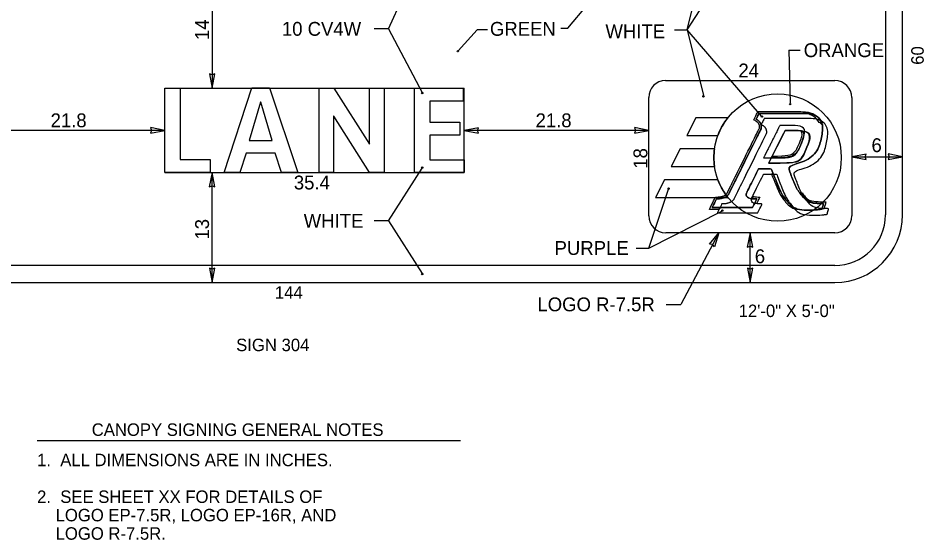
# Model space of a CAD drawing. Extents: x 60712 to 61344, y 9358 to 10016.
# Drawn here: x 60817.5 to 61020.9, y 9406.3 to 9523.5 of the extents above; entities that cross this region are included whole.
import ezdxf

# ---------------------------------------------------------------- set-up
doc = ezdxf.new("R2010")
doc.units = 0
for name, color, linetype in [('1', 7, 'Continuous'), ('52', 7, 'Continuous'), ('Default', 7, 'Continuous'), ('SignPanel', 7, 'Continuous'), ('TextNotes', 7, 'Continuous')]:
    doc.layers.add(name, color=color, linetype=linetype)

msp = doc.modelspace()

# ---------------------------------------------------------------- linework, layer by layer
at = {"layer": '1'}
for p, q in [((60967.73, 9520.86), (60980.08, 9540)), ((60900.69, 9521.08), (60907.15, 9535.36)), ((60967.73, 9520.86), (60971.4, 9535.64)), ((60940.98, 9521.26), (60945.38, 9526.45)), ((60900.69, 9521.08), (60897.49, 9521.08)), ((60900.69, 9521.08), (60908.25, 9506.8)), ((60920.6, 9520.86), (60916.35, 9516.16)), ((60922.88, 9520.86), (60920.6, 9520.86)), ((60939.35, 9521.26), (60940.98, 9521.26)), ((60964.88, 9520.86), (60967.73, 9520.86)), ((60967.73, 9520.86), (60971.4, 9506.08)), ((60984.44, 9501.48), (60967.73, 9520.86)), ((60990.58, 9516.29), (60993.13, 9516.29)), ((60990.58, 9516.29), (60990.88, 9504.35)), ((61004.73, 9492.36), (61016.13, 9492.36)), ((60900.69, 9477.96), (60908.25, 9489.76)), ((60959.13, 9471.85), (60963.59, 9485.04)), ((60959.13, 9471.85), (60975.54, 9480.16)), ((60900.69, 9477.96), (60897.49, 9477.96)), ((60900.69, 9477.96), (60908.25, 9466.16)), ((60974.83, 9475.26), (60966.36, 9459.17)), ((60981.88, 9464.1), (60981.88, 9475.26)), ((60956.28, 9471.85), (60959.13, 9471.85)), ((60963.03, 9459.17), (60966.36, 9459.17))]:
    msp.add_line(p, q, dxfattribs=at)
for centre, major_axis, ratio in [((60916.25, 9516.05), (0, 0.157), 0.906668), ((60908.25, 9506.64), (0.163, 0), 0.961364), ((60971.4, 9505.92), (0, 0.157), 0.906668), ((60990.88, 9504.19), (0, 0.157), 0.906668), ((60984.54, 9501.37), (0, 0.157), 0.906668), ((60908.25, 9489.91), (0.164, 0), 0.960359), ((60963.59, 9485.2), (0, 0.157), 0.906668), ((60975.65, 9480.27), (0, 0.157), 0.906668), ((60908.25, 9466), (0.163, 0), 0.961364)]:
    msp.add_ellipse(centre, major_axis=major_axis, ratio=ratio, dxfattribs=at)
at = {"layer": '52'}
for p, q in [((60861.05, 9510.73), (60860.45, 9510.98)), ((60860.45, 9510.98), (60861.05, 9507.75)), ((60861.05, 9507.75), (60861.67, 9510.98)), ((60861.67, 9510.98), (60861.05, 9510.73)), ((60850.44, 9498.28), (60847.22, 9498.9)), ((60847.22, 9498.9), (60847.46, 9498.28)), ((60847.46, 9498.28), (60847.22, 9497.68)), ((60847.22, 9497.68), (60850.44, 9498.28)), ((60920.9, 9498.88), (60917.68, 9498.28)), ((60917.68, 9498.28), (60920.9, 9497.66)), ((60920.66, 9498.28), (60920.9, 9498.88)), ((60920.9, 9497.66), (60920.66, 9498.28)), ((60959.13, 9498.28), (60955.9, 9498.9)), ((60955.9, 9498.9), (60956.15, 9498.28)), ((60956.15, 9498.28), (60955.9, 9497.68)), ((60955.9, 9497.68), (60959.13, 9498.28)), ((61007.95, 9492.96), (61004.73, 9492.36)), ((61004.73, 9492.36), (61007.95, 9491.73)), ((61007.7, 9492.36), (61007.95, 9492.96)), ((61007.95, 9491.73), (61007.7, 9492.36)), ((61016.13, 9492.36), (61012.9, 9492.98)), ((61012.9, 9492.98), (61013.15, 9492.36)), ((61013.15, 9492.36), (61012.9, 9491.76)), ((61012.9, 9491.76), (61016.13, 9492.36)), ((60861.05, 9488.8), (60860.42, 9485.58)), ((60861.65, 9485.58), (60861.05, 9488.8)), ((60860.42, 9485.58), (60861.05, 9485.82)), ((60861.05, 9485.82), (60861.65, 9485.58)), ((60972.8, 9472.69), (60974.83, 9475.26)), ((60974.83, 9475.26), (60973.88, 9472.12)), ((60981.88, 9475.26), (60981.26, 9472.04)), ((60982.48, 9472.04), (60981.88, 9475.26)), ((60973.44, 9472.62), (60972.8, 9472.69)), ((60973.88, 9472.12), (60973.44, 9472.62)), ((60981.26, 9472.04), (60981.88, 9472.28)), ((60981.88, 9472.28), (60982.48, 9472.04)), ((60861.05, 9467.08), (60860.45, 9467.32)), ((60860.45, 9467.32), (60861.05, 9464.1)), ((60861.05, 9464.1), (60861.67, 9467.32)), ((60861.67, 9467.32), (60861.05, 9467.08)), ((60981.88, 9467.08), (60981.28, 9467.32)), ((60981.28, 9467.32), (60981.88, 9464.1)), ((60981.88, 9464.1), (60982.5, 9467.32)), ((60982.5, 9467.32), (60981.88, 9467.08))]:
    msp.add_line(p, q, dxfattribs=at)
at = {"layer": 'Default'}
for p, q in [((60850.44, 9507.75), (60917.68, 9507.75)), ((60850.44, 9488.8), (60850.44, 9507.66)), ((60917.68, 9488.8), (60917.68, 9507.75)), ((60850.44, 9488.8), (60917.68, 9488.8))]:
    msp.add_line(p, q, dxfattribs=at)
at = {"layer": 'SignPanel'}
for p, q in [((61012.3, 9562.9), (61012.3, 9479.3)), ((61016.1, 9479.3), (61016.1, 9562.9)), ((60861.05, 9534.4), (60861.05, 9507.75)), ((60962.88, 9509.46), (61000.92, 9509.46)), ((60959.13, 9479.06), (60959.13, 9505.66)), ((61004.73, 9505.66), (61004.73, 9479.06)), ((60850.44, 9498.28), (60808.53, 9498.28)), ((60959.13, 9498.28), (60917.68, 9498.28)), ((60982.2, 9495.19), (60982.22, 9495.22)), ((60982.57, 9495.05), (60982.56, 9495.01)), ((60861.05, 9464.1), (60861.05, 9488.8)), ((60987.13, 9488.46), (60986.7, 9488.46)), ((60975.1, 9480.92), (60974.9, 9480.53)), ((61000.92, 9475.26), (60962.93, 9475.26)), ((61000.9, 9467.9), (60757.74, 9467.9)), ((60757.74, 9464.1), (61000.9, 9464.1))]:
    msp.add_line(p, q, dxfattribs=at)
for points in [[(60850.44, 9488.8), (60850.44, 9507.75), (60853.87, 9507.75), (60853.87, 9491.7), (60860.65, 9491.7), (60860.65, 9488.8), (60850.44, 9488.8)], [(60876.62, 9488.8), (60875.23, 9493.13), (60868.68, 9493.13), (60867.3, 9488.8), (60863.73, 9488.8), (60869.95, 9507.8), (60873.95, 9507.8), (60880.29, 9488.8), (60876.62, 9488.8)], [(60896.41, 9488.8), (60888.38, 9501.5), (60888.33, 9501.5), (60888.33, 9488.8), (60885.08, 9488.8), (60885.08, 9507.75), (60888.38, 9507.75), (60896.38, 9495.19), (60896.4, 9495.19), (60896.41, 9507.75), (60899.68, 9507.75), (60899.68, 9488.8), (60896.41, 9488.8)], [(60906.55, 9488.8), (60906.55, 9507.75), (60917.41, 9507.75), (60917.41, 9504.85), (60909.95, 9504.85), (60909.95, 9500.08), (60916.69, 9500.08), (60916.69, 9497.17), (60909.95, 9497.17), (60909.95, 9491.65), (60917.68, 9491.65), (60917.68, 9488.8), (60906.55, 9488.8)], [(60871.99, 9504.58), (60871.9, 9504.58), (60869.36, 9495.98), (60874.53, 9495.98), (60871.99, 9504.58)], [(60976.9, 9501.1), (60969.72, 9501.1), (60967.7, 9497.12), (60974.65, 9497.12)], [(60991.65, 9498.25), (60989.75, 9498.25), (60986.05, 9490.93), (60987.26, 9490.93)], [(60973.9, 9494.14), (60966.18, 9494.14), (60964.15, 9490.17), (60973.9, 9490.17)], [(60974.65, 9487.19), (60962.63, 9487.19), (60960.61, 9483.21), (60976.9, 9483.21)]]:
    msp.add_lwpolyline(points, dxfattribs=at)
msp.add_circle((60988.06, 9492.16), 14.31, dxfattribs=at)
for centre, radius, start, end in [((60962.93, 9505.66), 3.8, 90.6597, 180), ((61000.92, 9505.66), 3.8, 0, 90), ((60988.06, 9492.16), 14.31, 141.3093, 159.6812), ((60995.26, 9496.73), 3.97, 44.1751, 57.1095), ((60988.06, 9492.16), 14.31, 172.0148, 187.9874), ((60988.06, 9492.16), 14.31, 200.3256, 218.6989), ((61006.06, 9490.82), 14.13, 207.7086, 215.0356), ((60983.39, 9482.97), 1.08, 153.9516, 176.8436), ((60983.99, 9484.1), 2.29, 244.3445, 254.3668), ((60996.12, 9485.35), 6.28, 217.4324, 229.8152), ((60999.29, 9490.89), 10.19, 263.2057, 265.4782), ((60962.93, 9479.06), 3.8, 180, 270), ((61000.9, 9479.3), 15.2, 270, 0), ((61000.9, 9479.3), 11.4, 270, 0), ((61000.92, 9479.06), 3.8, 270, 360)]:
    msp.add_arc(centre, radius, start, end, dxfattribs=at)
for points, degree in [([(60982.22, 9495.22), (60983.25, 9497.3), (60983.98, 9498.77), (60983.98, 9498.77), (60983.98, 9498.77), (60983.99, 9498.89), (60983.99, 9498.89), (60983.99, 9498.89), (60983.99, 9499.07), (60983.99, 9499.07), (60983.99, 9499.07), (60983.99, 9499.2), (60983.99, 9499.2), (60983.99, 9499.2), (60983.98, 9499.34), (60983.98, 9499.34), (60983.98, 9499.34), (60983.94, 9499.51), (60983.94, 9499.51), (60983.94, 9499.51), (60983.87, 9499.7), (60983.87, 9499.7), (60983.87, 9499.7), (60983.8, 9499.81), (60983.8, 9499.81), (60983.8, 9499.81), (60983.67, 9499.98), (60983.67, 9499.98), (60983.67, 9499.98), (60983.48, 9500.15), (60983.48, 9500.15), (60983.48, 9500.15), (60983.26, 9500.3), (60983.26, 9500.3), (60983.26, 9500.3), (60982.72, 9500.63), (60982.72, 9500.63), (60982.72, 9500.63), (60983.65, 9502.48), (60983.65, 9502.48), (60983.65, 9502.48), (60992.81, 9502.48), (60992.81, 9502.48), (60995.67, 9502.48), (60997.43, 9501.23), (60998.1, 9499.5)], 3), ([(60983.76, 9489.61), (60983.76, 9489.61), (60981.33, 9484.71), (60981.33, 9484.71), (60980.89, 9483.99), (60981.21, 9482.91), (60983.43, 9482.91), (60983.43, 9482.91), (60982.44, 9480.92), (60982.44, 9480.92), (60982.44, 9480.92), (60973.37, 9480.92), (60973.37, 9480.92), (60973.37, 9480.92), (60974.37, 9482.91), (60974.37, 9482.91), (60974.37, 9482.91), (60974.65, 9482.91), (60974.65, 9482.91), (60974.65, 9482.91), (60974.95, 9482.92), (60974.95, 9482.92), (60974.95, 9482.92), (60975.21, 9482.95), (60975.21, 9482.95), (60975.21, 9482.95), (60975.65, 9483.04), (60975.65, 9483.04), (60975.65, 9483.04), (60975.99, 9483.13), (60975.99, 9483.13), (60975.99, 9483.13), (60976.27, 9483.25), (60976.27, 9483.25), (60976.27, 9483.25), (60976.47, 9483.36), (60976.47, 9483.36), (60976.47, 9483.36), (60976.67, 9483.48), (60976.67, 9483.48), (60976.67, 9483.48), (60976.87, 9483.67), (60976.87, 9483.67), (60976.87, 9483.67), (60977.02, 9483.86), (60977.02, 9483.86), (60977.02, 9483.86), (60977.07, 9483.97), (60977.07, 9483.97), (60977.07, 9483.97), (60984.36, 9498.65), (60984.36, 9498.65), (60984.36, 9498.65), (60984.39, 9498.87), (60984.39, 9498.87), (60984.39, 9498.87), (60984.39, 9499.07), (60984.39, 9499.07), (60984.39, 9499.07), (60984.39, 9499.22), (60984.39, 9499.22), (60984.39, 9499.22), (60984.38, 9499.4), (60984.38, 9499.4), (60984.38, 9499.4), (60984.32, 9499.63), (60984.32, 9499.63), (60984.32, 9499.63), (60984.23, 9499.87), (60984.23, 9499.87), (60984.23, 9499.87), (60984.13, 9500.03), (60984.13, 9500.03), (60984.13, 9500.03), (60983.96, 9500.26), (60983.96, 9500.26), (60983.96, 9500.26), (60983.72, 9500.46), (60983.72, 9500.46), (60983.72, 9500.46), (60983.48, 9500.64), (60983.48, 9500.64), (60983.48, 9500.64), (60983.24, 9500.78), (60983.24, 9500.78), (60983.24, 9500.78), (60983.89, 9502.08), (60983.89, 9502.08), (60983.89, 9502.08), (60992.81, 9502.08), (60992.81, 9502.08), (60996.85, 9502.08), (60998.48, 9499.63), (60997.91, 9496.76), (60997.28, 9493.58), (60994.23, 9491.09), (60990.08, 9490.36), (60990.99, 9488.67), (60992.07, 9485.42), (60993.63, 9483.48), (60994.68, 9482.17), (60996.52, 9481.85), (60998.39, 9481.85), (60998.39, 9481.85), (60998.03, 9480.58), (60998.03, 9480.58), (60998.03, 9480.58), (60997.78, 9480.54), (60997.78, 9480.54), (60996.75, 9480.4), (60996.09, 9480.37), (60995.33, 9480.37), (60992.8, 9480.37), (60991.25, 9481.1), (60990.06, 9482.58), (60988.67, 9484.31), (60987.33, 9487.99), (60986.66, 9489.61), (60986.66, 9489.61), (60983.76, 9489.61), (60983.76, 9489.61)], 3), ([(60984.92, 9488.46), (60984.92, 9488.46), (60982.49, 9483.55), (60982.49, 9483.55), (60982.05, 9482.84), (60982.36, 9481.75), (60984.59, 9481.75), (60984.59, 9481.75), (60983.59, 9479.77), (60983.59, 9479.77), (60983.59, 9479.77), (60974.53, 9479.77), (60974.53, 9479.77), (60974.53, 9479.77), (60975.52, 9481.75), (60975.52, 9481.75), (60975.52, 9481.75), (60975.8, 9481.75), (60975.8, 9481.75), (60975.8, 9481.75), (60976.11, 9481.77), (60976.11, 9481.77), (60976.11, 9481.77), (60976.36, 9481.79), (60976.36, 9481.79), (60976.36, 9481.79), (60976.8, 9481.89), (60976.8, 9481.89), (60976.8, 9481.89), (60977.14, 9481.98), (60977.14, 9481.98), (60977.14, 9481.98), (60977.42, 9482.1), (60977.42, 9482.1), (60977.42, 9482.1), (60977.62, 9482.21), (60977.62, 9482.21), (60977.62, 9482.21), (60977.82, 9482.33), (60977.82, 9482.33), (60977.82, 9482.33), (60978.02, 9482.52), (60978.02, 9482.52), (60978.02, 9482.52), (60978.17, 9482.71), (60978.17, 9482.71), (60978.17, 9482.71), (60978.22, 9482.81), (60978.22, 9482.81), (60978.22, 9482.81), (60985.51, 9497.5), (60985.51, 9497.5), (60985.51, 9497.5), (60985.54, 9497.71), (60985.54, 9497.71), (60985.54, 9497.71), (60985.54, 9497.91), (60985.54, 9497.91), (60985.54, 9497.91), (60985.54, 9498.06), (60985.54, 9498.06), (60985.54, 9498.06), (60985.53, 9498.25), (60985.53, 9498.25), (60985.53, 9498.25), (60985.47, 9498.48), (60985.47, 9498.48), (60985.47, 9498.48), (60985.38, 9498.72), (60985.38, 9498.72), (60985.38, 9498.72), (60985.29, 9498.88), (60985.29, 9498.88), (60985.29, 9498.88), (60985.11, 9499.11), (60985.11, 9499.11), (60985.11, 9499.11), (60984.87, 9499.31), (60984.87, 9499.31), (60984.87, 9499.31), (60984.63, 9499.48), (60984.63, 9499.48), (60984.63, 9499.48), (60984.39, 9499.63), (60984.39, 9499.63), (60984.39, 9499.63), (60985.05, 9500.93), (60985.05, 9500.93), (60985.05, 9500.93), (60993.96, 9500.93), (60993.96, 9500.93), (60998.01, 9500.93), (60999.63, 9498.48), (60999.06, 9495.61), (60998.43, 9492.42), (60995.38, 9489.94), (60991.23, 9489.21), (60992.14, 9487.52), (60993.23, 9484.27), (60994.78, 9482.33), (60995.83, 9481.02), (60997.67, 9480.69), (60999.55, 9480.69), (60999.55, 9480.69), (60999.18, 9479.42), (60999.18, 9479.42), (60999.18, 9479.42), (60998.94, 9479.39), (60998.94, 9479.39), (60997.91, 9479.25), (60997.24, 9479.22), (60996.48, 9479.22), (60993.96, 9479.22), (60992.41, 9479.94), (60991.21, 9481.43), (60989.83, 9483.16), (60988.48, 9486.84), (60987.82, 9488.46), (60987.82, 9488.46), (60984.92, 9488.46), (60984.92, 9488.46)], 3), ([(60982.57, 9495.05), (60983.6, 9497.12), (60984.36, 9498.65), (60984.36, 9498.65), (60984.36, 9498.65), (60984.39, 9498.87), (60984.39, 9498.87), (60984.39, 9498.87), (60984.39, 9499.07), (60984.39, 9499.07), (60984.39, 9499.07), (60984.39, 9499.22), (60984.39, 9499.22), (60984.39, 9499.22), (60984.38, 9499.4), (60984.38, 9499.4), (60984.38, 9499.4), (60984.32, 9499.63), (60984.32, 9499.63), (60984.32, 9499.63), (60984.23, 9499.87), (60984.23, 9499.87), (60984.23, 9499.87), (60984.13, 9500.03), (60984.13, 9500.03), (60984.13, 9500.03), (60983.96, 9500.26), (60983.96, 9500.26), (60983.96, 9500.26), (60983.72, 9500.46), (60983.72, 9500.46), (60983.72, 9500.46), (60983.48, 9500.64), (60983.48, 9500.64), (60983.48, 9500.64), (60983.24, 9500.78), (60983.24, 9500.78), (60983.24, 9500.78), (60983.89, 9502.08), (60983.89, 9502.08), (60983.89, 9502.08), (60992.81, 9502.08), (60992.81, 9502.08), (60996.85, 9502.08), (60998.48, 9499.63), (60997.91, 9496.76), (60997.28, 9493.58), (60994.23, 9491.09), (60990.08, 9490.36), (60990.99, 9488.67), (60992.07, 9485.42), (60993.63, 9483.48), (60994.68, 9482.17), (60996.52, 9481.85), (60998.39, 9481.85), (60998.39, 9481.85), (60998.03, 9480.58), (60998.03, 9480.58), (60998.03, 9480.58), (60997.78, 9480.54), (60997.78, 9480.54), (60996.75, 9480.4), (60996.09, 9480.37), (60995.33, 9480.37), (60992.8, 9480.37), (60991.25, 9481.1), (60990.06, 9482.58), (60988.67, 9484.31), (60987.33, 9487.99), (60986.66, 9489.61), (60986.66, 9489.61), (60983.76, 9489.61), (60983.76, 9489.61)], 3), ([(60997.41, 9500.06), (60996.64, 9501.28), (60995.12, 9502.08), (60992.81, 9502.08), (60992.81, 9502.08), (60983.89, 9502.08), (60983.89, 9502.08), (60983.89, 9502.08), (60983.24, 9500.78), (60983.24, 9500.78), (60983.24, 9500.78), (60983.48, 9500.64), (60983.48, 9500.64), (60983.48, 9500.64), (60983.72, 9500.46), (60983.72, 9500.46), (60983.72, 9500.46), (60983.96, 9500.26), (60983.96, 9500.26), (60983.96, 9500.26), (60984.13, 9500.03), (60984.13, 9500.03), (60984.13, 9500.03), (60984.23, 9499.87), (60984.23, 9499.87), (60984.23, 9499.87), (60984.32, 9499.63), (60984.32, 9499.63), (60984.32, 9499.63), (60984.38, 9499.4), (60984.38, 9499.4), (60984.38, 9499.4), (60984.39, 9499.22), (60984.39, 9499.22), (60984.39, 9499.22), (60984.39, 9499.07), (60984.39, 9499.07), (60984.39, 9499.07), (60984.39, 9498.87), (60984.39, 9498.87), (60984.39, 9498.87), (60984.36, 9498.65), (60984.36, 9498.65), (60984.36, 9498.65), (60983.6, 9497.12), (60982.57, 9495.05)], 3), ([(60985.61, 9493.5), (60985.19, 9492.66), (60984.9, 9492.08), (60984.9, 9492.08), (60984.9, 9492.08), (60986.11, 9492.08), (60986.11, 9492.08), (60990.09, 9492.08), (60992.23, 9492.37), (60993.57, 9495.83), (60994.49, 9498.23), (60993.47, 9499.4), (60990.49, 9499.4), (60990.49, 9499.4), (60988.59, 9499.4), (60988.59, 9499.4)], 3), ([(60988.59, 9499.4), (60988.59, 9499.4), (60986.71, 9495.66), (60985.63, 9493.53)], 2), ([(60989.75, 9498.25), (60989.75, 9498.25), (60986.05, 9490.93), (60986.05, 9490.93), (60986.05, 9490.93), (60987.26, 9490.93), (60987.26, 9490.93), (60991.24, 9490.93), (60993.38, 9491.22), (60994.72, 9494.68), (60995.65, 9497.08), (60994.62, 9498.25), (60991.65, 9498.25), (60991.65, 9498.25), (60989.75, 9498.25), (60989.75, 9498.25)], 3), ([(60987.26, 9490.93), (60991.24, 9490.93), (60993.38, 9491.22), (60994.72, 9494.68), (60995.65, 9497.08), (60994.62, 9498.25), (60991.65, 9498.25)], 3), ([(60993.82, 9497.92), (60993.98, 9497.38), (60993.9, 9496.68), (60993.57, 9495.83), (60992.29, 9492.53), (60990.28, 9492.12), (60986.64, 9492.08)], 3), ([(60986.84, 9492.48), (60990.3, 9492.52), (60992.02, 9492.94), (60993.2, 9495.98), (60993.55, 9496.9), (60993.62, 9497.58), (60993.37, 9498.06)], 3), ([(60993.37, 9498.06), (60993.53, 9498.02), (60993.68, 9497.98), (60993.82, 9497.92)], 2), ([(60974.9, 9480.53), (60973.64, 9480.53), (60972.73, 9480.53), (60972.73, 9480.53), (60972.73, 9480.53), (60974.12, 9483.3), (60974.12, 9483.3), (60974.12, 9483.3), (60974.64, 9483.3), (60974.64, 9483.3), (60974.64, 9483.3), (60974.93, 9483.32), (60974.93, 9483.32), (60974.93, 9483.32), (60975.15, 9483.34), (60975.15, 9483.34), (60975.15, 9483.34), (60975.56, 9483.43), (60975.56, 9483.43), (60975.56, 9483.43), (60975.85, 9483.51), (60975.85, 9483.51), (60975.85, 9483.51), (60976.1, 9483.61), (60976.1, 9483.61), (60976.1, 9483.61), (60976.27, 9483.71), (60976.27, 9483.71), (60976.27, 9483.71), (60976.43, 9483.8), (60976.43, 9483.8), (60976.43, 9483.8), (60976.58, 9483.94), (60976.58, 9483.94), (60976.58, 9483.94), (60976.68, 9484.07), (60976.68, 9484.07), (60976.68, 9484.07), (60976.71, 9484.14), (60976.71, 9484.14), (60976.71, 9484.14), (60980.04, 9490.84), (60982.2, 9495.19)], 3), ([(60983.76, 9489.61), (60983.76, 9489.61), (60981.33, 9484.71), (60981.33, 9484.71), (60980.89, 9483.99), (60981.21, 9482.91), (60983.43, 9482.91), (60983.43, 9482.91), (60982.44, 9480.92), (60982.44, 9480.92), (60982.44, 9480.92), (60973.37, 9480.92), (60973.37, 9480.92), (60973.37, 9480.92), (60974.37, 9482.91), (60974.37, 9482.91), (60974.37, 9482.91), (60974.65, 9482.91), (60974.65, 9482.91), (60974.65, 9482.91), (60974.95, 9482.92), (60974.95, 9482.92), (60974.95, 9482.92), (60975.21, 9482.95), (60975.21, 9482.95), (60975.21, 9482.95), (60975.65, 9483.04), (60975.65, 9483.04), (60975.65, 9483.04), (60975.99, 9483.13), (60975.99, 9483.13), (60975.99, 9483.13), (60976.27, 9483.25), (60976.27, 9483.25), (60976.27, 9483.25), (60976.47, 9483.36), (60976.47, 9483.36), (60976.47, 9483.36), (60976.67, 9483.48), (60976.67, 9483.48), (60976.67, 9483.48), (60976.87, 9483.67), (60976.87, 9483.67), (60976.87, 9483.67), (60977.02, 9483.86), (60977.02, 9483.86), (60977.02, 9483.86), (60977.07, 9483.97), (60977.07, 9483.97), (60977.07, 9483.97), (60980.4, 9490.66), (60982.56, 9495.01)], 3), ([(60982.56, 9495.01), (60980.4, 9490.66), (60977.07, 9483.97), (60977.07, 9483.97), (60977.07, 9483.97), (60977.02, 9483.86), (60977.02, 9483.86), (60977.02, 9483.86), (60976.87, 9483.67), (60976.87, 9483.67), (60976.87, 9483.67), (60976.67, 9483.48), (60976.67, 9483.48), (60976.67, 9483.48), (60976.47, 9483.36), (60976.47, 9483.36), (60976.47, 9483.36), (60976.27, 9483.25), (60976.27, 9483.25), (60976.27, 9483.25), (60975.99, 9483.13), (60975.99, 9483.13), (60975.99, 9483.13), (60975.65, 9483.04), (60975.65, 9483.04), (60975.65, 9483.04), (60975.21, 9482.95), (60975.21, 9482.95), (60975.21, 9482.95), (60974.95, 9482.92), (60974.95, 9482.92), (60974.95, 9482.92), (60974.65, 9482.91), (60974.65, 9482.91), (60974.65, 9482.91), (60974.37, 9482.91), (60974.37, 9482.91), (60974.37, 9482.91), (60973.37, 9480.92), (60973.37, 9480.92), (60973.37, 9480.92), (60974.08, 9480.92), (60975.1, 9480.92)], 3), ([(60986.64, 9492.08), (60986.7, 9492.21), (60986.77, 9492.34), (60986.84, 9492.48)], 2), ([(60986.7, 9488.46), (60987.37, 9486.78), (60988.54, 9483.85), (60989.75, 9482.33), (60990.38, 9481.54), (60991.14, 9480.95), (60992.07, 9480.55)], 3), ([(60991.13, 9481.53), (60990.74, 9481.83), (60990.39, 9482.18), (60990.06, 9482.58), (60988.94, 9483.97), (60987.86, 9486.63), (60987.13, 9488.46)], 3), ([(60993.55, 9484.25), (60993.68, 9484.07), (60993.8, 9483.89), (60993.94, 9483.73), (60994.9, 9482.53), (60996.55, 9482.24), (60998.92, 9482.24), (60998.92, 9482.24), (60998.66, 9481.33), (60998.49, 9480.73)], 3), ([(60983, 9482.04), (60983.22, 9482.49), (60983.43, 9482.91), (60983.43, 9482.91), (60982.99, 9482.91), (60982.62, 9482.95), (60982.32, 9483.03)], 3), ([(60982.43, 9483.44), (60982.81, 9483.35), (60983.35, 9483.3), (60984.08, 9483.3), (60984.08, 9483.3), (60983.72, 9482.6), (60983.37, 9481.9)], 3), ([(60998.09, 9480.77), (60998.19, 9481.13), (60998.39, 9481.85), (60998.39, 9481.85), (60996.96, 9481.85), (60995.55, 9482.03), (60994.49, 9482.71)], 3)]:
    msp.add_open_spline(points, degree=degree, dxfattribs=at)
at = {"layer": 'TextNotes'}
msp.add_line((60821.75, 9428.64), (60916.85, 9428.64), dxfattribs=at)

# ---------------------------------------------------------------- texts
at = {"layer": '1'}
for s, height, p in [('14', 3.111, (60860.36, 9518.57)), ('60', 2.8, (61020.88, 9513.01)), ('18', 3.111, (60958.81, 9489.66)), ('13', 3.111, (60860.36, 9473.75))]:
    msp.add_text(s, height=height, rotation=90, dxfattribs=at).set_placement(p)
for s, height, p in [('10 CV4W', 3.111, (60876.73, 9519.52)), ('GREEN', 3.111, (60923.45, 9519.52)), ('WHITE', 3.111, (60949.4, 9518.96)), ('ORANGE', 3.111, (60993.93, 9514.73)), ('24', 3.111, (60979.26, 9510.17)), ('21.8', 3.111, (60824.78, 9498.97)), ('21.8', 3.111, (60933.7, 9498.97)), ('6', 3.11, (61009.15, 9493.39)), ('35.4', 3.111, (60879.41, 9485)), ('WHITE', 3.111, (60881.63, 9476.4)), ('PURPLE', 3.111, (60937.97, 9470.29)), ('6', 3.11, (60982.94, 9468.44)), ('144', 2.8, (60875.15, 9460.45)), ('LOGO R-7.5R', 3.1111, (60934.12, 9457.63)), ('12\'-0" X 5\'-0"', 2.8, (60979.32, 9456.34)), ('SIGN 304', 2.8, (60866.46, 9448.68))]:
    msp.add_text(s, height=height, dxfattribs=at).set_placement(p)
at = {"layer": 'TextNotes'}
for s, p in [('CANOPY SIGNING GENERAL NOTES', (60834.02, 9429.65)), ('1.  ALL DIMENSIONS ARE IN INCHES.', (60821.75, 9422.84)), ('2.  SEE SHEET XX FOR DETAILS OF', (60821.75, 9414.58)), ('    LOGO EP-7.5R, LOGO EP-16R, AND', (60821.75, 9410.45)), ('    LOGO R-7.5R.', (60821.75, 9406.32))]:
    msp.add_text(s, height=2.8, dxfattribs=at).set_placement(p)

doc.saveas('drawing.dxf')
